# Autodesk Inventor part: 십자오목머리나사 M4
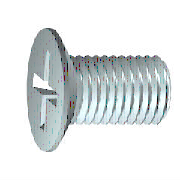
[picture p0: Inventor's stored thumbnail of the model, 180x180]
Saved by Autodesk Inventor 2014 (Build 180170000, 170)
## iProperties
IsCustomPart: 0
Created: 2012-02
Part Number: 십자오목머리나사 M4
Material: 강철, 연강
Description: 십자 오목 머리 나사
Document SubType Name: Modeling
Standard: KS B 1023
Designer: mduedu
Standards Organization: KS
Language: ko-KR
Size Designation: A  M 4 x 12 - H
Categories: <MemberInstance><Categories><Category DisplayName="조임쇠" InternalName="e4da775c-781d-43d5-af7c-5136215cf5a6" Mnemonic="FSTN"><Category DisplayName="볼트" InternalN
Density: 7.86 g/cm^3
Mass: 1.5048 g
Surface Area: 2.78557 cm^2
Volume: 0.191451 cm^3
Appearance: 주황색
Author: mduedu
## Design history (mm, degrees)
body "Solid1"
sketch "스케치1"
  geometry: L1 (2.6, 0)-(12, 0); L2 (12, 0)-(12, 2); L3 (12, 2)-(4.1, 2); L4 (4.1, 2)-(3.671, 1.785); L5 (3.671, 1.785)-(2.7, 1.785); L6 (0, 4.2)-(0, 2.4); L7 (0, 2.4)-(1.801, 1.502); L8 (1.801, 1.502)-(2.6, 0); L9 (-2.4, 0)-(14.4, 0) reference; L10 (0, -0.84)-(0, 5.04) reference; L11 (0, 4.2)-(0.285, 4.2); L12 (0.285, 4.2)-(2.7, 1.785); L13 (4.1, 2)-(2.485, 2)
  constraints: 22 end point, 3 parallel, 3 perpendicular, 2 collinear, 1 horizontal, 1 point on line
  dimensions: "d1" = 7.9 distance of L2.end L3.end (= GEL); "d2" = 4 diameter of L3 L1 (= GD); "d3" = 3.57058 diameter of L5 L1 (= BDM); "d4" = 4.8 diameter of L6.end L1 (= SDM); "d5" = 26.5 deg angle of L7 L1; "d6" = 62 deg angle of L8 L1; "d7" = 2.6 distance from line of L1.start L6 (= INTI); "d8" = 0.42941 horizontal distance of L4.end L3.end (= GAL); "d12" = 8.4 diameter of L11 L1 (= KOD); "d13" = 45 deg angle of L12 L1 (= 0.5 x SEWI); "d15" = 12 distance between parallel lines of L2 L6 (= NLG); "d24" = 2.7 distance from line of L5.end L6 (= KOH)
revolve "본체" stored, may be unused: angle "d16" = 90 deg
sketch "스케치2"
  geometry: L1 (0, 2.4)-(0, 0); L2 (0, 0)-(2.4, 0); L3 (0, 0)-(1.697, 1.697); L4 (0.312, 2.38)-(0.408, 0.734); L5 (2.38, 0.312)-(0.734, 0.408); L6 (0, -5.88)-(0, 5.88) reference; L7 (-5.88, 0)-(5.88, 0) reference; L8 (2.38, -0.312)-(0.734, -0.408); L9 (0.312, -2.38)-(0.408, -0.734); L10 (-0.312, -2.38)-(-0.408, -0.734); L11 (-2.38, -0.312)-(-0.734, -0.408); L12 (-2.38, 0.312)-(-0.734, 0.408); L13 (-0.312, 2.38)-(-0.408, 0.734); A1 r 0.72 centre (0, 0) between (0.72, 0) and (0, 0.72); A2 r 0.84 centre (0, 0) between (0.84, 0) and (0, 0.84); A3 r 2.4 centre (0, 0) between (2.38, 0.312) and (0.312, 2.38); A4 r 2.4 centre (0, 0) between (0.312, 2.38) and (0, 2.4); A5 r 2.4 centre (0, 0) between (2.4, 0) and (2.38, 0.312); A6 r 2.4 centre (0, 0) between (0, -2.4) and (0.312, -2.38); A7 r 2.4 centre (0, 0) between (0.312, -2.38) and (2.38, -0.312); A8 r 2.4 centre (0, 0) between (2.38, -0.312) and (2.4, 0); A9 r 2.4 centre (0, 0) between (0, 2.4) and (-0.312, 2.38); A10 r 2.4 centre (0, 0) between (-0.312, 2.38) and (-2.38, 0.312); A11 r 2.4 centre (0, 0) between (-2.38, 0.312) and (-2.4, 0); A12 r 2.4 centre (0, 0) between (-2.4, 0) and (-2.38, -0.312); A13 r 2.4 centre (0, 0) between (-2.38, -0.312) and (-0.312, -2.38); A14 r 2.4 centre (0, 0) between (-0.312, -2.38) and (0, -2.4); A15 r 0.347 centre (0.755, 0.755) between (0.408, 0.734) and (0.734, 0.408); A16 r 0.347 centre (0.755, -0.755) between (0.734, -0.408) and (0.408, -0.734); A17 r 0.347 centre (-0.755, -0.755) between (-0.408, -0.734) and (-0.734, -0.408); A18 r 0.347 centre (-0.755, 0.755) between (-0.734, 0.408) and (-0.408, 0.734); 3 further points
  constraints: 41 point on circle, 22 end point, 22 symmetric about line, 18 centre point, 11 coincident, 4 point on line, 3 tangent, 2 collinear, 1 perpendicular, 1 vertical, 19 other
  dimensions: "d17" = 1.44 diameter of A1 (= 0.3 x SDM); "d18" = 1.68 diameter of A2 (= 0.35 x SDM); "d19" = 4.8 diameter of A3 (= SDM); "d20" = 45 deg angle of L3 L2; "d21" = 0.3115 distance from line of L4.start L1 (= 0.5 x SBR)
extrude "슬롯" join sketch "스케치2" taper "d22" = 5 deg; stored distance "d79" = 25.4
fillet "모깎기1" dims "d23" = 0.1246 (= 0.2 x SBR)
feature "스레드" dims "d10" = 7.9 (= GEL), "d11" = 0
chamfer "모따기1" distance "d25" = 0.42941 (= -0.5 x SPD + 0.5 x GD); stored, may be unused: second distance "d26" = 0.21471 (= 0.5 x GAL), angle "d88" = 45 deg
workplane "Work Plane2"
other parameters: "NLG" = 12 [user parameter; used in 1 equation term], "GEL" = 7.9 [user parameter; used in 2 equation terms], "GAL" = 0.42941 (= 0.61345 x PTC) [user parameter; used in 3 equation terms], "SPD" = 3.14117 (= NND - 1.2269 x PTC) [user parameter; used in 1 equation term], "KOD" = 8.4 [user parameter; used in 1 equation term], "KOH" = 2.7 [user parameter; used in 1 equation term], "SBR" = 0.623 [user parameter; used in 2 equation terms], "INTI" = 2.6 [user parameter; used in 1 equation term], "SDM" = 4.8 [user parameter; used in 5 equation terms], "GD" = 4 (= NND) [user parameter; used in 2 equation terms], "BDM" = 3.57058 (= NND - GAL) [user parameter; used in 1 equation term], "SEWI" = 90 deg [user parameter; used in 1 equation term], "d9" = 4.8 (= SDM), "d27" = 0, "d91" = 0, "d92" = 0, "GUL" = 0.42941 (= 0.61345 x PTC) [user parameter], "TOA" = 30 deg [user parameter], "EPV" = 4.7 [user parameter], "THREADDIA" = 4 [user parameter; used in 1 equation term], "TPU" = 14.28571 (computed from PTC) [user parameter], "PTC" = 0.7 [user parameter; used in 5 equation terms], "NND" = 4 [user parameter; used in 3 equation terms], "GD1" = 3.14117 (= THREADDIA - 1.2269 x PTC) [user parameter]
